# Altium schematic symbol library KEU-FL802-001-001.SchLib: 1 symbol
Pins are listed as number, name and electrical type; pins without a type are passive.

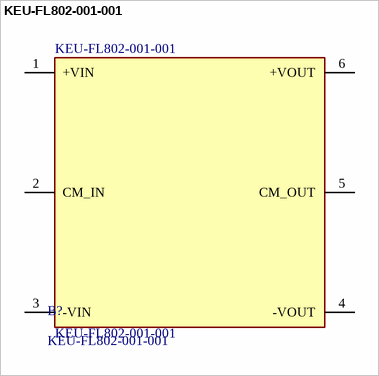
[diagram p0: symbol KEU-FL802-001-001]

## KEU-FL802-001-001
designator B?
30Aout Passive Quarter EMI Filter Brick; MFG: KOLT
footprint KEU-FL802-001-001
pins: 1 +VIN, 2 CM_IN, 3 -VIN, 4 -VOUT, 5 CM_OUT, 6 +VOUT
